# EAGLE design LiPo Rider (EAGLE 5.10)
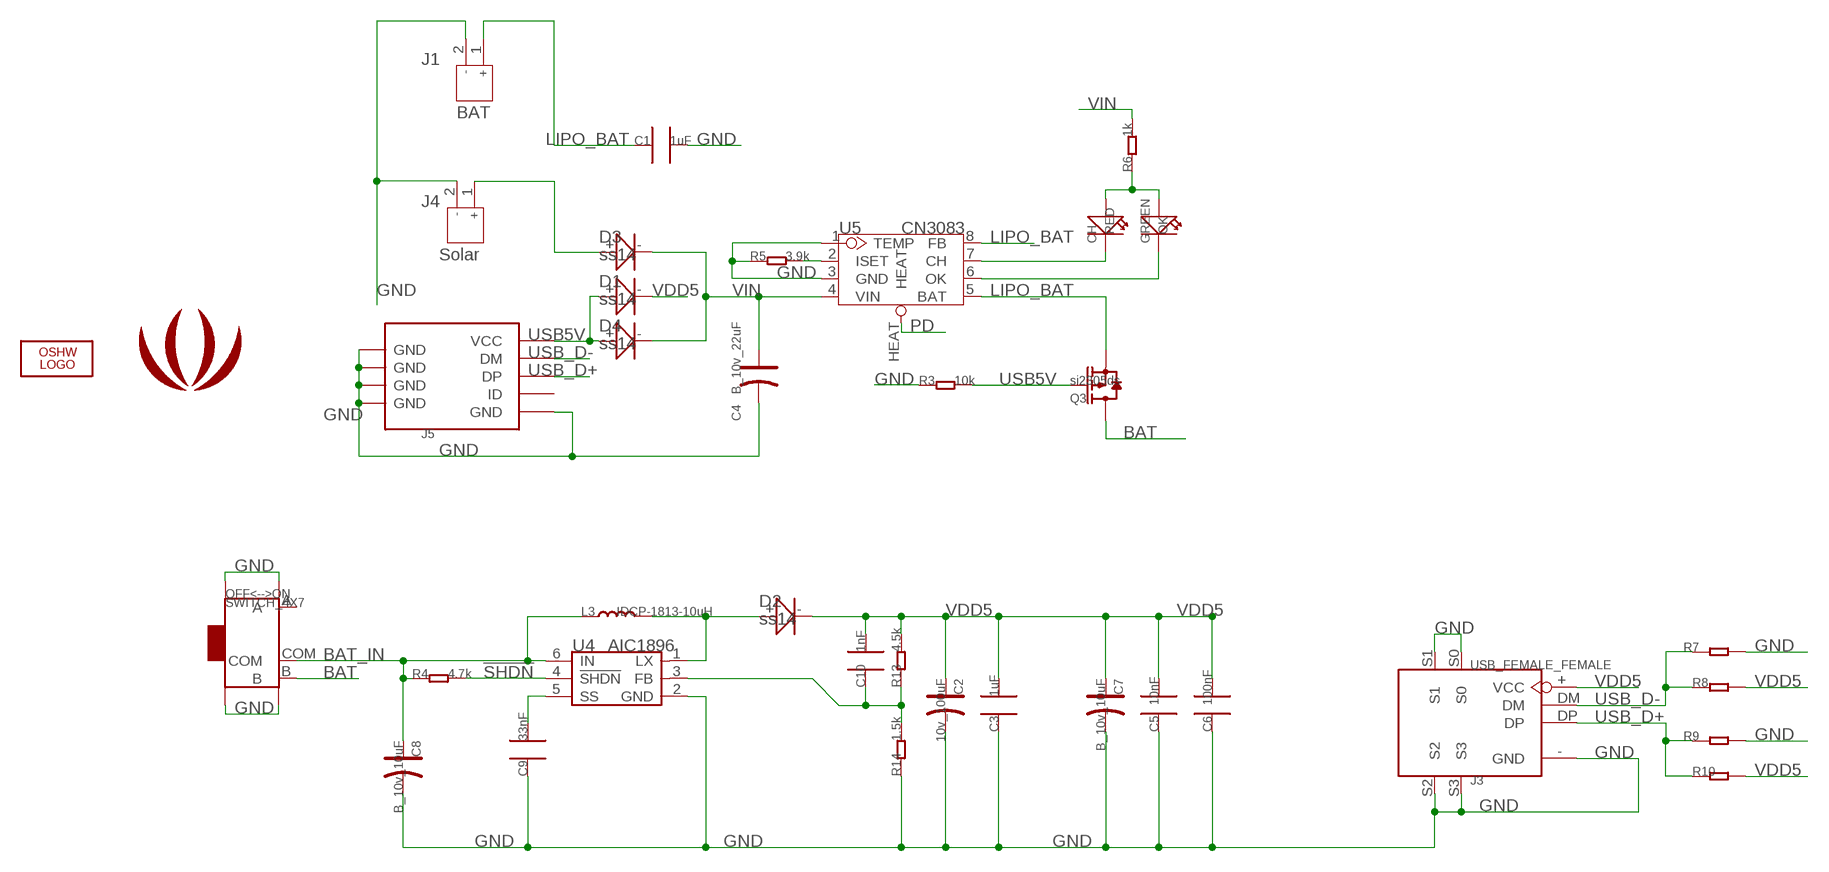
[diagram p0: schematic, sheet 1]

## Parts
C1  1uF  C0805  [0805]
C2  10v_100uF  006-CAP_AVX_C  [AVX_C]
C3  1uF  C0805  [0805]
C4  B_10v_22uF  006-CAP_AVX_B  [AVX_B]
C5  10nF  006-C0603  [0603]
C6  100nF  006-C0603  [0603]
C7  B_10v_10uF  006-CAP_AVX_B  [AVX_B]
C8  B_10v_10uF  006-CAP_AVX_B  [AVX_B]
C9  33nF  C0603  [0603]
C10  1nF  C0603  [0603]
CH  RED  LED0603_DD  [LED0603]
D1  ss14  010-D2010  [D2010]
D2  ss14  010-D2010  [D2010]
D3  ss14  010-D2010  [D2010]
D4  ss14  010-D2010  [D2010]
J1  BAT  JACK-JST-2P-PW'SMD'  [JST-SMD-2.0]
J3  USB_FEMALE_FEMALE  USB_FEMALEHHS  [USB_FEMALE_HALF]
J4  Solar  JACK-JST-2P-PW'SMD'  [JST-SMD-2.0]
J5  USB-MINIUSB-5P-STRONG  [MINI-SMD-5P]
L3  IDCP-1813-10uH  013-L1813  [1813]
LOGO2  LOGO-OSHW-FILLX0200-NT  [OSHW_FILLX200_NOTEXT]
OFF<-->ON  SWITCH_4X7  [4*8_SW]
OK  GREEN  LED0603_DD  [LED0603]
Q3  si2305ds  010-P-MOSFETSOT23  [SOT23]
R3  10k  R0603  [0603]
R4  4.7k  R0603  [0603]
R5  3.9k  R0603  [0603]
R6  1k  R0603  [0603]
R7  005-R0204/5  [0204/5]
R8  005-R0204/5  [0204/5]
R9  005-R0204/5  [0204/5]
R10  005-R0204/5  [0204/5]
R13  4.5k  R0603  [0603]
R14  1.5k  R0603  [0603]
U4  AIC1896  [SOT23-6]
U5  CN3083  [SOP8]
U$1  LOGO-SEEEDSTUDIO-SILK  [LOGO_SILK]

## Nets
!SHDN: R4.2 U4.4(!SHDN)
BAT: OFF<-->ON.B Q3.3(D)
BAT_IN: C8.+ L3.1 OFF<-->ON.COM R4.1 U4.6(IN)
GND: C1.2 C2.- C3.1 C4.- C5.1 C6.1 C7.- C8.- C9.1 J1.2 J3.-(GND) J3.S0 J3.S1 J3.S2 J3.S3 J4.2 J5.5(GND) J5.GND@1(GND) J5.GND@2(GND) J5.GND@3(GND) J5.GND@4(GND) OFF<-->ON.SS1 OFF<-->ON.SS2 OFF<-->ON.SS3 OFF<-->ON.SS4 R3.1 R5.1 R7.2 R9.2 R14.1 U4.2(GND) U5.1(TEMP) U5.3(GND)
LIPO_BAT: C1.1 J1.1 Q3.2(S) U5.5(BAT) U5.8(FB)
N$3: D3.+ J4.1
N$6: C9.2 U4.5(SS)
N$7: D2.+ L3.2 U4.1(LX)
N$8: C10.1 R13.1 R14.2 U4.3(FB)
N$13: R5.2 U5.2(ISET)
N$14: CH.2(-) U5.7(CH)
N$15: OK.2(-) U5.6(OK)
N$16: CH.1(+) OK.1(+) R6.1
PD: U5.HEAT
USB5V: D1.+ D4.+ J5.1(VCC) Q3.1(G) R3.2
USB_D+: J3.DP J5.3(DP) R9.1 R10.1
USB_D-: J3.DM J5.2(DM) R7.1 R8.1
VDD5: C2.+ C3.2 C5.2 C6.2 C7.+ C10.2 D1.- D2.- J3.+(VCC) R8.2 R10.2 R13.2
VIN: C4.+ D3.- D4.- R6.2 U5.4(VIN)
Unconnected: J5.4(ID) OFF<-->ON.A

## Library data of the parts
C1 C3 = CPT_SMD:C0805
C2 C4 C7 C8 = Discrete:006-CAP*: Electrolytic Capacitors,Tantalum Capacitors and Super Capacitors
C5 C6 = Discrete:006-C*: Ceramic Capacitors
C9 C10 = CPT_SMD:C0603; C0603: 100N
CH OK = CPT_SMD:LED0603
D1-D4 = Discrete:010-D*
J1 J4 = Connector:JACK-JST-2P-PW
J3 = CONNECTER:USB_FEMALE
J5 = Connector:USB-MINIUSB-5P
L3 = Discrete:013-L*
LOGO2 = logo:LOGO-OSHW-FILL
OFF<-->ON = CPT_SMD:SWITCH
Q3 = Discrete:010-P-MOSFET*: Si2305DS Si2323CDS
R3-R6 R13 R14 = CPT_SMD:R0603
R7-R10 = Discrete:005-R*
U4 = ICs_v54:AIC1896
U5 = ICs_v54:CN3083
U$1 = logo:LOGO-SEEEDSTUDIO

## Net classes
0 default: width 0.203 mm, drill 0.305 mm, clearance 0.127 mm

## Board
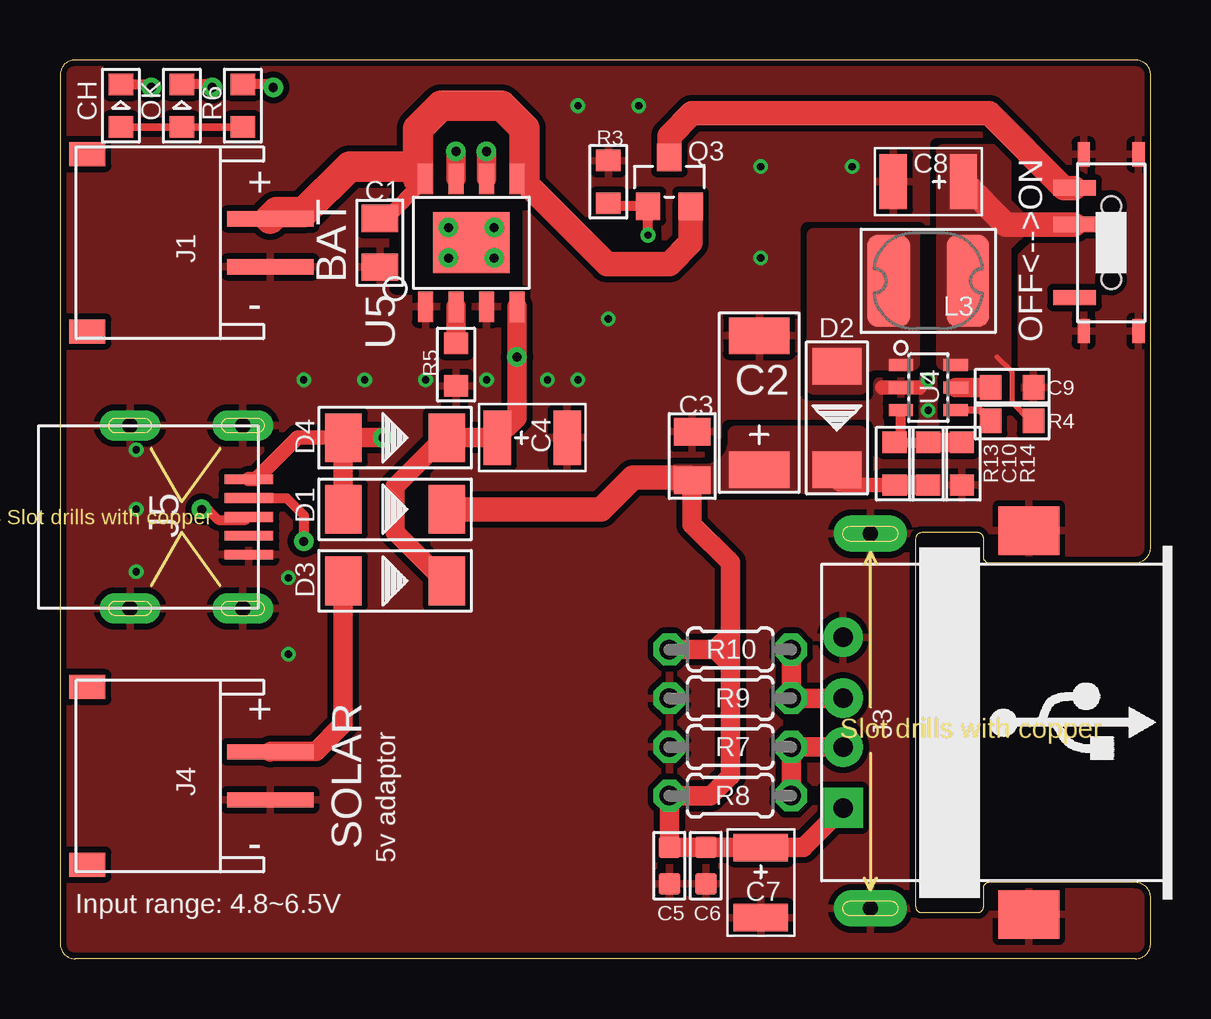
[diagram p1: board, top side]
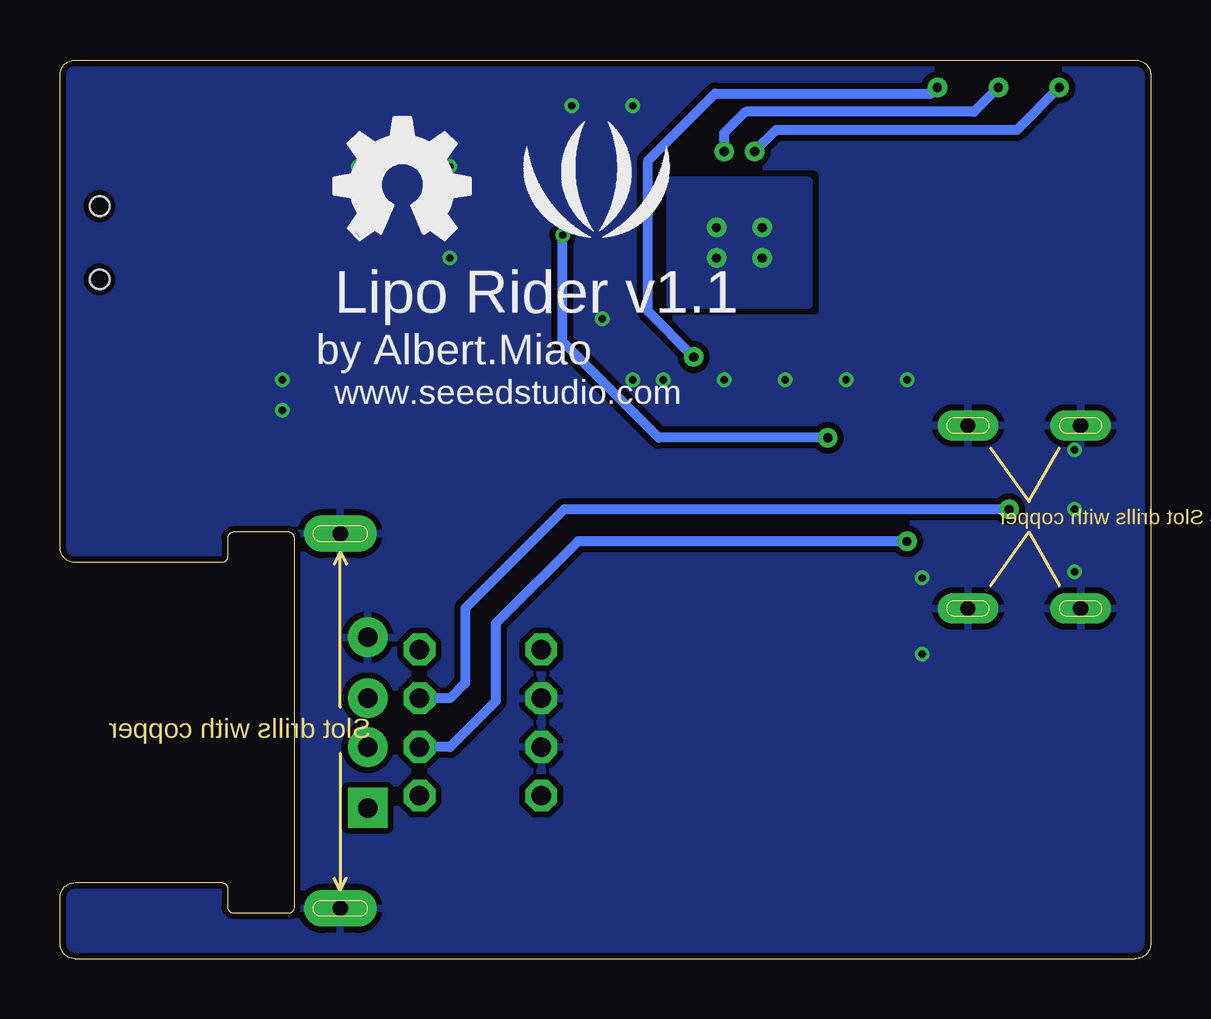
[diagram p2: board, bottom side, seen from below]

Size 45.47 x 37.47 mm. Coordinates in mm from the lower left corner, seen from the top.
Outline: 0.64,37.47 arc90 0,36.83 0,0.64 arc90 0.64,0 44.83,0 arc90 45.47,0.64 45.47,2.54 arc90 44.83,3.17 38.73,3.17 arc90 38.48,2.92 38.48,2.16 arc-90 38.23,1.91 35.94,1.91 arc-90 35.69,2.16 35.69,17.53 arc-90 35.94,17.78 38.23,17.78 arc-90 38.48,17.53 38.48,16.76 arc90 38.73,16.51 44.83,16.51 arc90 45.47,17.14 45.47,36.83 arc90 44.83,37.47 0.64,37.47
Copper layers (1*16): Top 0.035mm / dielectric 1.5mm / Bottom 0.035mm
Design rules "SeeedStudio_rule_no_angle_090911 *": minimum track width 6mil, minimum drill 12mil, track to track 6mil, track to pad 5mil, pad to pad 5mil, via to via 6mil, smd to smd 0mil, copper to edge 10mil, drill to drill 10mil, minimum pad ring 10mil, minimum via ring 6mil, stop-mask expansion 2mil, vias tented up to drill 100mil, thermal gap 10mil
tRestrict: area 14,27.9 to 19.1,31.8

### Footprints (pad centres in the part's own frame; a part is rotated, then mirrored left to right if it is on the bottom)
0805 = smd 1.143 x 1.524: 1 -1.016,0; 2 1.016,0
AVX_C = smd 1.524 x 2.54: + -2.794,0; - 2.794,0
AVX_B = smd 1.143 x 2.286: + -1.46,0; - 1.46,0
0603@1 = smd 0.889 x 0.889: 1 -0.762,0; 2 0.762,0
0603 = smd 0.889 x 1.016: 1 -0.889,0; 2 0.889,0
LED0603 = smd 0.889 x 1.016: 1 -0.889,0; 2 0.889,0
D2010 = smd 1.524 x 2.032: + -2.159,0; - 2.159,0
JST-SMD-2.0 = smd 0.635 x 3.6: 1 -1,5.08; 2 1,5.08 | smd 1 x 1.5: P$1 -3.7,-2.54; P$2 3.7,-2.54
USB_FEMALE_HALF = drill 0.813 pad 1.651 square: + 0.889,-3.556 | drill 0.813 pad 1.651 round: - 0.889,3.556; DM 0.889,-1.016; DP 0.889,1.016 | smd 2.54 x 2.032: S0 8.636,8.001; S3 8.636,-8.001 | drill 0.635 pad 1.524 long: S1 2.032,7.874; S2 2.032,-7.747
MINI-SMD-5P = smd 2.032 x 0.406: 1 0.381,-1.575; 2 0.381,-0.787; 3 0.381,0; 4 0.381,0.787; 5 0.381,1.575 | drill 0.635 pad 1.27 long: GND@1 0.635,3.81; GND@2 5.334,3.81; GND@3 5.334,-3.81; GND@4 0.635,-3.81
1813 = smd 1.778 x 3.81: 1 -1.651,0; 2 1.651,0
4*8_SW = smd 1.778 x 0.635: A 1.524,2.286; B 1.524,-2.286; COM 1.524,-0.762 | smd 0.508 x 1.016: SS1 -1.143,-3.683; SS2 1.143,-3.683; SS3 1.143,3.683; SS4 -1.143,3.683 | hole 0.813: 0,-1.524; 0,1.524
SOT23@1 = smd 1.016 x 1.143: 1 -0.889,-1.016; 2 0.889,-1.016; 3 0,1.016
0204/5 = drill 0.813 octagon: 1 -2.54,0; 2 2.54,0
SOT23-6 = smd 0.508 x 1.016: 1 -0.94,-1.143; 2 0,-1.143; 3 0.94,-1.143; 4 0.94,1.143; 5 0,1.143; 6 -0.94,1.143
SOP8 = smd 0.635 x 1.27: 1 -1.905,-2.667; 2 -0.635,-2.667; 3 0.635,-2.667; 4 1.905,-2.667; 5 1.905,2.667; 6 0.635,2.667; 7 -0.635,2.667; 8 -1.905,2.667 | smd 3.175 x 2.54: HEAT 0,0

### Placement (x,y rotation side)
C1  13.34,29.84 270 top
C2  29.15,23.18 90 top
C3  26.35,20.95 270 top
C4  19.68,21.72 0 top
C5  10nF  [0603@1]  25.4,3.87 90 top
C6  100nF  [0603@1]  26.92,3.87 90 top
C7  29.21,3.17 270 top
C8  36.2,32.38 180 top
C9  39.69,23.81 180 top
C10  36.2,20.64 270 top
CH  2.54,35.56 90 top
D1  13.97,18.73 0 top
D2  32.38,22.54 270 top
D3  13.97,15.75 0 top
D4  13.97,21.72 0 top
J1  3.68,29.84 270 top
J3  31.75,9.84 0 top
J4  3.68,7.62 270 top
J5  8.26,18.41 180 top
L3  36.2,28.26 180 top
LOGO2  34.04,29.97 0 bottom
OFF<-->ON  43.81,29.84 180 top
OK  5.08,35.56 90 top
Q3  si2305ds  [SOT23@1]  25.4,32.38 0 top
R3  22.86,32.38 270 top
R4  39.69,22.42 180 top
R5  16.51,24.77 90 top
R6  7.62,35.56 90 top
R7  27.94,8.83 180 top
R8  27.94,6.79 180 top
R9  27.94,10.86 180 top
R10  27.94,12.89 180 top
R13  34.8,20.64 270 top
R14  37.59,20.64 90 top
U4  36.2,23.81 270 top
U5  17.14,29.84 0 top
U$1  23.11,31.75 0 bottom

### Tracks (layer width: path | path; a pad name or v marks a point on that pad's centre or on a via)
!SHDN
  Top 0.305: U4.4 38.34,22.87 R4.2
BAT
  Top 1.016: OFF<-->ON.B 41.85,32.13 38.73,35.24 26.35,35.24 25.4,34.29 Q3.3
BAT_IN
  Top 0.203: 39.69,23.18 39.69,24.45 39.05,25.08
  Top 0.254: R4.1 40.45,22.42 39.69,23.18
  Top 1.016: OFF<-->ON.COM 39.43,30.61 C8.+
  pour Top (isolate 0.254, no thermals): 39.37,24.83 36.83,24.83 36.83,33.66 39.37,33.66 39.37,31.5 40.26,30.61 39.37,29.72
GND  (via drill 0.3)
  Top 0.61: 35.81,23.81 U4.2 34.29,23.81
  other vias: 36.2,24.13 36.2,22.86 3.17,18.73 3.17,21.21 3.17,16.13 9.53,15.88 9.53,12.7 33.02,33.02 29.21,33.02 29.21,29.21 17.78,24.13 15.24,24.13 12.7,24.13 10.16,24.13 21.59,35.56 24.13,35.56 20.32,24.13 21.59,24.13 22.86,26.67
  pour Top: -5.08,38.1 -3.81,38.1 -3.81,36.83 -5.08,36.83
  pour Top (isolate 0.254, rank 6): -0.64,38.1 46.35,38.1 46.35,-0.64 -0.64,-0.64
  pour Bottom (isolate 0.254, rank 6): -0.64,38.1 46.35,38.1 46.35,-0.64 -0.64,-0.64
LIPO_BAT
  Top 0.61: 14.92,33.34 15.24,33.02 U5.8 13.46,30.73 C1.1 | 19.37,32.51 U5.5
  Top 1.016: 19.37,32.51 19.37,32.38 22.8,28.96 25.4,28.96 26.29,29.84 Q3.2
  Top 1.27: 14.92,33.02 14.92,33.34 14.92,34.61 15.88,35.56 18.41,35.56 19.37,34.61 19.37,32.51 | 14.92,33.02 14.92,32.51 | 14.92,33.02 12.06,33.02 10.16,31.11 9.03,31.11 J1.1
N$3
  Top 0.813: D3.+ 11.81,9.78 10.67,8.64 8.78,8.64 J4.1
N$6
  Top 0.813: U4.5 C9.2
N$7
  pour Top (isolate 0.254, no thermals): 35.56,24.83 33.97,24.83 arc90 33.34,24.19 33.34,23.81 31.43,23.81 31.43,30.16 35.56,30.16
N$8
  Top 0.406: U4.3 35.05,21.78 R13.1 C10.1
  Top 0.813: C10.1 R14.2
N$13
  Top 0.813: R5.2 U5.2
N$14  (via drill 0.38 pad 0.81)
  Top 0.254: CH.2 2.67,36.32
  Top 0.406: CH.2 3.68,36.45 v3.81,36.32
  Top 0.813: v16.51,33.66 U5.7
  Bottom 0.406: v3.81,36.32 5.59,34.54 15.62,34.54 v16.51,33.66
N$15  (via drill 0.38 pad 0.81)
  Top 0.406: OK.2 6.22,36.45 v6.35,36.32
  Top 0.813: v17.78,33.66 U5.6
  Bottom 0.406: v6.35,36.32 7.37,35.31 16.89,35.31 17.78,34.42 v17.78,33.66
N$16
  Top 0.305: CH.1 OK.1 R6.1
PD  (via drill 0.38 pad 0.81)
  Top 0.406: v16.19,29.21 16.51,29.21 U5.HEAT | v16.19,30.48 16.51,30.48 U5.HEAT | v18.1,29.21 17.78,29.21 U5.HEAT | v18.1,30.48 17.78,30.48 U5.HEAT
  pour Bottom (isolate 0.305): 14.29,32.38 20,32.38 20,27.3 14.29,27.3
USB5V  (via drill 0.3, 0.38 pad 0.81)
  Top 0.406: v24.51,30.16 Q3.1 22.99,31.37 R3.2
  Top 0.61: J5.1 8.18,19.99 9.91,21.72 D4.+
  Top 0.813: v13.46,21.72 D4.+ D1.+
  Bottom 0.406: v13.46,21.72 20.51,21.72 24.51,25.72 v24.51,30.16
USB_D+  (via drill 0.38 pad 0.81)
  Top 0.406: v5.91,18.73 6.16,18.73 6.6,18.29 7.75,18.29 J5.3
  Top 0.813: J3.DP R9.1 R10.1
  Bottom 0.406: v5.91,18.73 24.45,18.73 28.57,14.61 28.57,11.49 29.21,10.86 R9.1
USB_D-  (via drill 0.38 pad 0.81)
  Top 0.406: v10.16,17.4 10.16,18.49 9.45,19.2 J5.2
  Top 0.813: J3.DM R7.1 R8.1
  Bottom 0.406: v10.16,17.4 23.88,17.4 27.3,13.97 27.3,10.73 29.21,8.83 R7.1
VDD5
  Top 0.61: R13.2 32.64,19.75 32.51,19.88
  Top 0.813: R13.2 C10.2 | 32.51,19.88 32.38,20 | J3.+ 30.99,4.64 C7.+ C6.2 | 27.94,12.26 27.94,7.62 27.11,6.79 R8.2 C5.2 C6.2 | 27.94,12.26 27.94,13.97 | 27.94,12.26 27.3,12.89 | 27.3,12.89 27.94,13.53 27.94,16.51 26.35,18.1 C3.2 | 27.3,12.89 R10.2 | C6.2 26.67,4.64
  Top 1.016: D1.- 22.54,18.73 23.88,20.07 26.23,20.07 C3.2
  pour Top (isolate 0.254, no thermals): 33.34,19.68 25.72,19.68 25.72,20.32 26.86,20.32 arc90 28.13,21.59 28.13,21.91 33.34,21.91
VIN  (via drill 0.38 pad 0.81)
  Top 0.406: R6.2 8.76,36.45 v8.89,36.32
  Top 0.813: U5.4 v19.05,25.08 19.05,22.54 C4.+ D4.- 16,21.72 13.97,19.68 13.97,17.78 16,15.75 D3.-
  Bottom 0.406: v19.05,25.08 20.95,26.99 20.95,33.27 18.16,36.07 9.14,36.07 v8.89,36.32

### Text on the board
tPlace: + | BAT | - | + | SOLAR | - | 5v adaptor | Input range: 4.8~6.5V
bPlace: Lipo Rider v1.1 | by Albert.Miao | www.seeedstudio.com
